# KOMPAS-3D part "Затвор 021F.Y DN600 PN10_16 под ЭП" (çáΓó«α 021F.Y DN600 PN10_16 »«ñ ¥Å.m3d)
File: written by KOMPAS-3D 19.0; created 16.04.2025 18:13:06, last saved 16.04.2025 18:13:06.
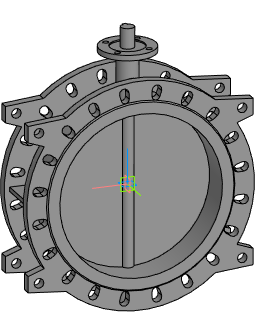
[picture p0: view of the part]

Document properties: Автор: Евгений; Полное имя файла: E:\Dendor Работа Сачек\3D для проекитирвщиков\1.6 Тип 021F.Y Затвор дисковый поворотный фланцевый\stp_Тип 021F.Y Затвор  DN40 PN10_16 под ЭП\Затвор 021F.Y DN600 PN10_16 под ЭП.m3d

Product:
- Part/product: Затвор 021F.Y DN600 PN10_16 под ЭП

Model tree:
1. Операция без истории:1  (labels: Затвор 021F.Y DN600 PN10_16 под ЭП)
